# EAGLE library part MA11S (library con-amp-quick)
AMP QUICK CONNECTOR
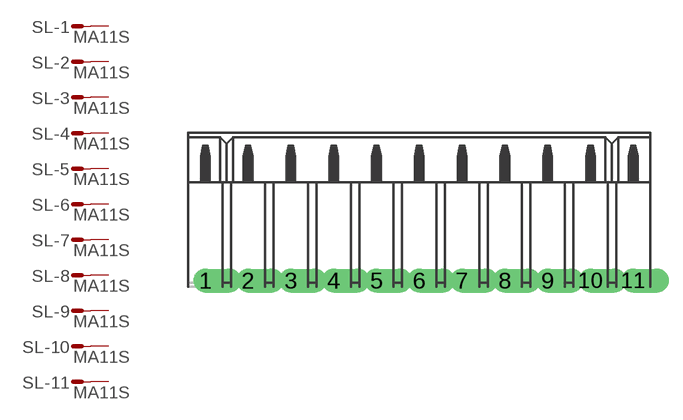
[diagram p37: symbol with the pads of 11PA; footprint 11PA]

Designator prefix SL; gates -1=M -2=M -3=M -4=M -5=M -6=M -7=M -8=M -9=M -10=M -11=M

## MA11S  [11PA]
1  -1:S  pas
2  -2:S  pas
3  -3:S  pas
4  -4:S  pas
5  -5:S  pas
6  -6:S  pas
7  -7:S  pas
8  -8:S  pas
9  -9:S  pas
10  -10:S  pas
11  -11:S  pas

## Footprint 11PA (pad centres in mm)
AMP QUICK CONNECTOR
drill 0.914 offset: 1 -12.7,0; 2 -10.16,0; 3 -7.62,0; 4 -5.08,0; 5 -2.54,0; 6 0,0; 7 2.54,0; 8 5.08,0; 9 7.62,0; 10 10.16,0; 11 12.7,0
